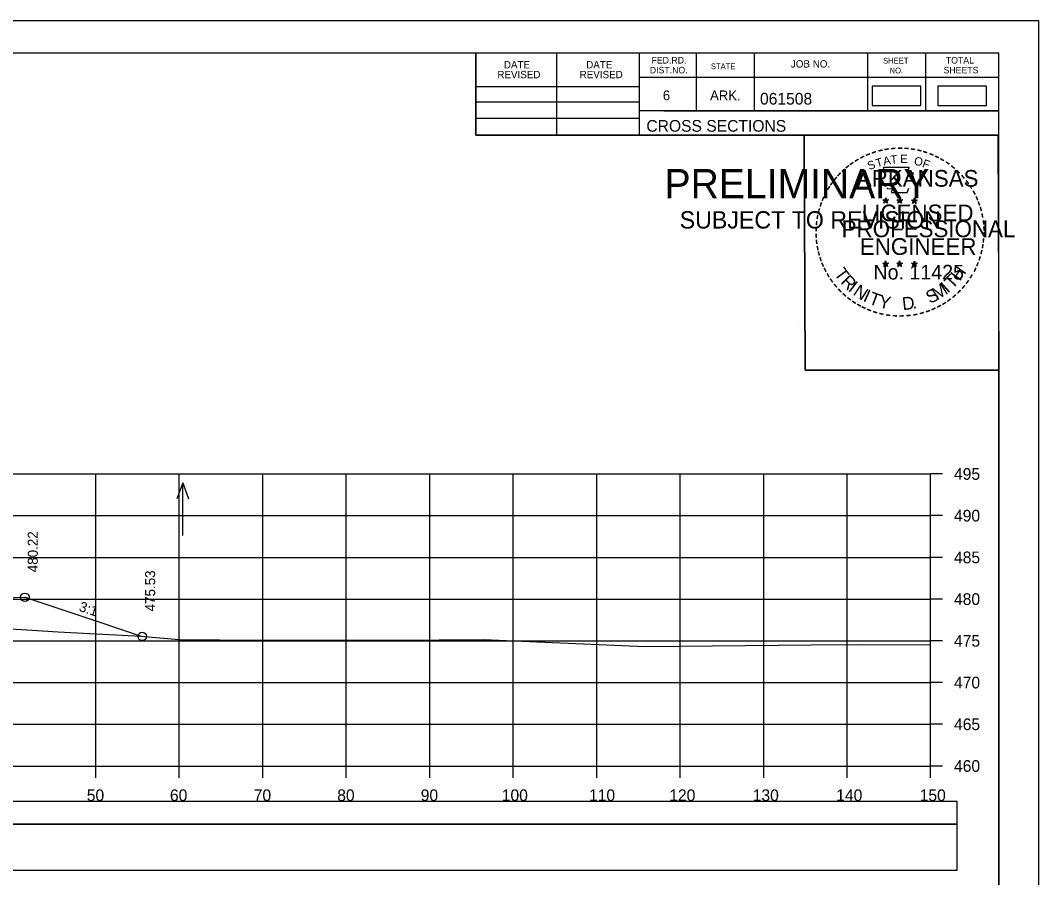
# Model space of a CAD drawing. Extents: x 1371057 to 1372761, y 380005 to 390517.
# Drawn here: x 1371601.8 to 1371723.8, y 382249.1 to 382351.8 of the extents above; entities that cross this region are included whole.
import ezdxf

# ---------------------------------------------------------------- set-up
doc = ezdxf.new("R2010")
doc.units = 0
for name, color, linetype in [('R_Axis', 7, 'Continuous'), ('R_Axis Annot', 7, 'Continuous'), ('R_Border', 7, 'Continuous'), ('R_Border PE', 7, 'Continuous'), ('R_Border Prem', 7, 'Continuous'), ('R_Detour', 7, 'Continuous'), ('R_Dimension', 7, 'Continuous'), ('R_Exist Surface', 7, 'Continuous'), ('R_Fin Surface', 7, 'Continuous'), ('R_Grid', 7, 'Continuous'), ('R_No Plot', 7, 'Continuous'), ('R_Water Annot', 7, 'Continuous'), ('R_Xsect Elev', 7, 'Continuous'), ('R_Xsect Slope', 7, 'Continuous')]:
    doc.layers.add(name, color=color, linetype=linetype)

msp = doc.modelspace()

# ---------------------------------------------------------------- linework, layer by layer
at = {"layer": 'R_Axis'}
for p, q in [((1371710.87, 382262.44), (1371710.87, 382297.44)), ((1371712.27, 382297.44), (1371710.87, 382297.44)), ((1371712.27, 382292.44), (1371710.87, 382292.44)), ((1371712.27, 382287.44), (1371710.87, 382287.44)), ((1371712.27, 382282.44), (1371710.87, 382282.44)), ((1371712.27, 382277.44), (1371710.87, 382277.44)), ((1371712.27, 382272.44), (1371710.87, 382272.44)), ((1371712.27, 382267.44), (1371710.87, 382267.44)), ((1371410.87, 382262.44), (1371710.87, 382262.44)), ((1371610.87, 382261.04), (1371610.87, 382262.44)), ((1371620.87, 382261.04), (1371620.87, 382262.44)), ((1371630.87, 382261.04), (1371630.87, 382262.44)), ((1371640.87, 382261.04), (1371640.87, 382262.44)), ((1371650.87, 382261.04), (1371650.87, 382262.44)), ((1371660.87, 382261.04), (1371660.87, 382262.44)), ((1371670.87, 382261.04), (1371670.87, 382262.44)), ((1371680.87, 382261.04), (1371680.87, 382262.44)), ((1371690.87, 382261.04), (1371690.87, 382262.44)), ((1371700.87, 382261.04), (1371700.87, 382262.44)), ((1371710.87, 382261.04), (1371710.87, 382262.44)), ((1371712.27, 382262.44), (1371710.87, 382262.44))]:
    msp.add_line(p, q, dxfattribs=at)
at = {"layer": 'R_Border'}
for p, q in [((1371402.87, 382347.9), (1371719.05, 382347.9)), ((1371656.41, 382338.02), (1371656.41, 382347.9)), ((1371666.09, 382338.02), (1371666.09, 382347.9)), ((1371675.95, 382347.9), (1371675.95, 382338.02)), ((1371682.79, 382347.9), (1371682.79, 382340.96)), ((1371689.73, 382347.9), (1371689.73, 382340.96)), ((1371703.31, 382347.9), (1371703.31, 382340.96)), ((1371710.25, 382347.9), (1371710.25, 382340.96)), ((1371719.05, 382142.44), (1371719.05, 382347.9)), ((1371719.05, 382344.96), (1371675.95, 382344.96)), ((1371719.05, 382344.98), (1371719.05, 382344.98)), ((1371656.41, 382343.88), (1371675.95, 382343.88)), ((1371656.41, 382342.02), (1371675.95, 382342.02)), ((1371656.41, 382340.08), (1371675.95, 382340.08)), ((1371719.05, 382340.96), (1371675.95, 382340.96)), ((1371678.91, 382340.96), (1371719.05, 382340.96)), ((1371719.05, 382338.02), (1371656.41, 382338.02))]:
    msp.add_line(p, q, dxfattribs=at)
at = {"layer": 'R_Border PE'}
for p, q in [((1371705.14, 382330.27), (1371705.49, 382330.16)), ((1371705.14, 382330.27), (1371705.39, 382330.23)), ((1371705.14, 382330.27), (1371705.37, 382330.15)), ((1371705.27, 382329.87), (1371705.49, 382330.16)), ((1371705.27, 382329.87), (1371705.4, 382330.11)), ((1371705.27, 382329.87), (1371705.48, 382330.08)), ((1371705.49, 382330.53), (1371705.45, 382330.28)), ((1371705.7, 382329.87), (1371705.48, 382330.08)), ((1371705.49, 382330.16), (1371705.49, 382330.53)), ((1371705.49, 382330.53), (1371705.54, 382330.28)), ((1371705.83, 382330.27), (1371705.49, 382330.16)), ((1371705.7, 382329.87), (1371705.49, 382330.16)), ((1371705.83, 382330.27), (1371705.55, 382330.23)), ((1371705.7, 382329.87), (1371705.56, 382330.16)), ((1371705.83, 382330.27), (1371705.63, 382330.17)), ((1371706.81, 382330.27), (1371707.16, 382330.16)), ((1371706.81, 382330.27), (1371707.06, 382330.23)), ((1371706.81, 382330.27), (1371707.04, 382330.15)), ((1371706.94, 382329.87), (1371707.16, 382330.16)), ((1371706.94, 382329.87), (1371707.07, 382330.11)), ((1371706.94, 382329.87), (1371707.15, 382330.08)), ((1371707.16, 382330.53), (1371707.12, 382330.28)), ((1371707.37, 382329.87), (1371707.15, 382330.08)), ((1371707.16, 382330.16), (1371707.16, 382330.53)), ((1371707.16, 382330.53), (1371707.21, 382330.28)), ((1371707.5, 382330.27), (1371707.16, 382330.16)), ((1371707.37, 382329.87), (1371707.16, 382330.16)), ((1371707.5, 382330.27), (1371707.22, 382330.23)), ((1371707.37, 382329.87), (1371707.23, 382330.16)), ((1371707.5, 382330.27), (1371707.3, 382330.17)), ((1371708.57, 382330.26), (1371708.92, 382330.15)), ((1371708.57, 382330.26), (1371708.82, 382330.22)), ((1371708.57, 382330.26), (1371708.81, 382330.14)), ((1371708.7, 382329.85), (1371708.92, 382330.15)), ((1371708.7, 382329.85), (1371708.83, 382330.1)), ((1371708.7, 382329.85), (1371708.92, 382330.07)), ((1371708.92, 382330.52), (1371708.88, 382330.26)), ((1371708.92, 382330.15), (1371708.92, 382330.52)), ((1371708.92, 382330.52), (1371708.97, 382330.27)), ((1371709.27, 382330.26), (1371708.92, 382330.15)), ((1371709.13, 382329.85), (1371708.92, 382330.15)), ((1371709.13, 382329.85), (1371708.92, 382330.07)), ((1371709.27, 382330.26), (1371708.98, 382330.21)), ((1371709.13, 382329.85), (1371709, 382330.15)), ((1371709.27, 382330.26), (1371709.06, 382330.16)), ((1371705.13, 382322.7), (1371705.48, 382322.59)), ((1371705.13, 382322.7), (1371705.39, 382322.66)), ((1371705.13, 382322.7), (1371705.37, 382322.58)), ((1371705.48, 382322.96), (1371705.44, 382322.7)), ((1371705.48, 382322.59), (1371705.48, 382322.96)), ((1371705.48, 382322.96), (1371705.53, 382322.71)), ((1371705.83, 382322.7), (1371705.48, 382322.59)), ((1371705.83, 382322.7), (1371705.54, 382322.65)), ((1371705.83, 382322.7), (1371705.63, 382322.6)), ((1371706.8, 382322.7), (1371707.15, 382322.59)), ((1371706.8, 382322.7), (1371707.06, 382322.66)), ((1371706.8, 382322.7), (1371707.04, 382322.58)), ((1371707.15, 382322.96), (1371707.11, 382322.7)), ((1371707.15, 382322.59), (1371707.15, 382322.96)), ((1371707.15, 382322.96), (1371707.2, 382322.71)), ((1371707.5, 382322.7), (1371707.15, 382322.59)), ((1371707.5, 382322.7), (1371707.21, 382322.65)), ((1371707.5, 382322.7), (1371707.29, 382322.6)), ((1371708.57, 382322.69), (1371708.92, 382322.58)), ((1371708.57, 382322.69), (1371708.82, 382322.65)), ((1371708.57, 382322.69), (1371708.81, 382322.57)), ((1371708.92, 382322.95), (1371708.88, 382322.69)), ((1371708.92, 382322.58), (1371708.92, 382322.95)), ((1371708.92, 382322.95), (1371708.97, 382322.7)), ((1371709.27, 382322.69), (1371708.92, 382322.58)), ((1371709.27, 382322.69), (1371708.98, 382322.64)), ((1371709.27, 382322.69), (1371709.06, 382322.59)), ((1371705.27, 382322.29), (1371705.48, 382322.59)), ((1371705.27, 382322.29), (1371705.39, 382322.54)), ((1371705.27, 382322.29), (1371705.48, 382322.51)), ((1371705.7, 382322.29), (1371705.48, 382322.59)), ((1371705.7, 382322.29), (1371705.48, 382322.51)), ((1371705.7, 382322.29), (1371705.56, 382322.58)), ((1371706.94, 382322.29), (1371707.15, 382322.59)), ((1371706.94, 382322.29), (1371707.06, 382322.54)), ((1371706.94, 382322.29), (1371707.15, 382322.51)), ((1371707.36, 382322.29), (1371707.15, 382322.59)), ((1371707.36, 382322.29), (1371707.15, 382322.51)), ((1371707.36, 382322.29), (1371707.23, 382322.58)), ((1371708.7, 382322.28), (1371708.92, 382322.58)), ((1371708.7, 382322.28), (1371708.83, 382322.53)), ((1371708.7, 382322.28), (1371708.92, 382322.5)), ((1371709.13, 382322.28), (1371708.92, 382322.58)), ((1371709.13, 382322.28), (1371708.92, 382322.5)), ((1371709.13, 382322.28), (1371708.99, 382322.57))]:
    msp.add_line(p, q, dxfattribs=at)
for points in [[(1371705.18, 382334.15), (1371705.45, 382333.33)], [(1371708.69, 382333.23), (1371708.83, 382333.51), (1371708.15, 382333.49), (1371708.29, 382334.15), (1371705.18, 382334.15)], [(1371705.67, 382331.73), (1371705.67, 382331.64), (1371706.23, 382331.62), (1371706.18, 382331.15), (1371708.05, 382331.15), (1371708.25, 382331.69)], [(1371705.49, 382330.53), (1371705.7, 382329.87), (1371705.14, 382330.27), (1371705.83, 382330.27), (1371705.27, 382329.87), (1371705.49, 382330.53)], [(1371707.16, 382330.53), (1371707.37, 382329.87), (1371706.81, 382330.27), (1371707.5, 382330.27), (1371706.94, 382329.87), (1371707.16, 382330.53)], [(1371708.92, 382330.52), (1371709.13, 382329.85), (1371708.57, 382330.26), (1371709.27, 382330.26), (1371708.7, 382329.85), (1371708.92, 382330.52)], [(1371705.48, 382322.96), (1371705.7, 382322.29), (1371705.13, 382322.7), (1371705.83, 382322.7), (1371705.27, 382322.29), (1371705.48, 382322.96)], [(1371707.15, 382322.96), (1371707.36, 382322.29), (1371706.8, 382322.7), (1371707.5, 382322.7), (1371706.94, 382322.29), (1371707.15, 382322.96)], [(1371708.92, 382322.95), (1371709.13, 382322.28), (1371708.57, 382322.69), (1371709.27, 382322.69), (1371708.7, 382322.28), (1371708.92, 382322.95)]]:
    msp.add_lwpolyline(points, dxfattribs=at)
for centre, radius in [((1371705.49, 382330.16), 0.172), ((1371705.49, 382330.16), 0.145), ((1371705.49, 382330.16), 0.116), ((1371705.49, 382330.16), 0.0991), ((1371705.49, 382330.16), 0.0747), ((1371705.49, 382330.16), 0.0495), ((1371705.49, 382330.16), 0.0296), ((1371707.16, 382330.16), 0.172), ((1371707.16, 382330.16), 0.145), ((1371707.16, 382330.16), 0.116), ((1371707.16, 382330.16), 0.0991), ((1371707.16, 382330.16), 0.0747), ((1371707.16, 382330.16), 0.0495), ((1371707.16, 382330.16), 0.0296), ((1371708.92, 382330.15), 0.172), ((1371708.92, 382330.15), 0.145), ((1371708.92, 382330.15), 0.116), ((1371708.92, 382330.15), 0.0991), ((1371708.92, 382330.15), 0.0747), ((1371708.92, 382330.15), 0.0495), ((1371708.92, 382330.15), 0.0296), ((1371705.48, 382322.59), 0.172), ((1371705.48, 382322.59), 0.145), ((1371705.48, 382322.59), 0.116), ((1371705.48, 382322.59), 0.0991), ((1371707.15, 382322.59), 0.172), ((1371707.15, 382322.59), 0.145), ((1371707.15, 382322.59), 0.116), ((1371707.15, 382322.59), 0.0991), ((1371708.92, 382322.58), 0.172), ((1371708.92, 382322.58), 0.145), ((1371708.92, 382322.58), 0.116), ((1371705.48, 382322.59), 0.0747), ((1371705.48, 382322.59), 0.0495), ((1371705.48, 382322.59), 0.0296), ((1371707.15, 382322.59), 0.0747), ((1371707.15, 382322.59), 0.0495), ((1371707.15, 382322.59), 0.0296), ((1371708.92, 382322.58), 0.0991), ((1371708.92, 382322.58), 0.0747), ((1371708.92, 382322.58), 0.0495), ((1371708.92, 382322.58), 0.0296)]:
    msp.add_circle(centre, radius, dxfattribs=at)
at = {"layer": 'R_Detour'}
msp.add_lwpolyline([(1371407.72, 382255.49), (1371714.03, 382255.49), (1371714.03, 382258.19), (1371407.72, 382258.19)], close=True, dxfattribs=at)
at = {"layer": 'R_Dimension'}
for points in [[(1371703.87, 382341.61), (1371709.7, 382341.61), (1371709.7, 382343.92), (1371703.87, 382343.92)], [(1371711.74, 382341.61), (1371717.57, 382341.61), (1371717.57, 382343.92), (1371711.74, 382343.92)], [(1371407.72, 382249.96), (1371714.03, 382249.96), (1371714.03, 382255.49), (1371407.72, 382255.49)]]:
    msp.add_lwpolyline(points, close=True, dxfattribs=at)
at = {"layer": 'R_Exist Surface'}
msp.add_lwpolyline([(1371597.54, 382279.09), (1371606.38, 382278.5), (1371616.25, 382277.99), (1371621.29, 382277.55), (1371625.73, 382277.55), (1371646.32, 382277.53), (1371647.2, 382277.52), (1371652.01, 382277.54), (1371655.8, 382277.55), (1371657.32, 382277.58), (1371675.7, 382276.8), (1371676.8, 382276.76), (1371696.54, 382276.97), (1371702.69, 382276.99), (1371710.87, 382276.97)], dxfattribs=at)
at = {"layer": 'R_Fin Surface'}
msp.add_lwpolyline([(1371599.81, 382282.61), (1371602.37, 382282.66), (1371610.99, 382279.78), (1371616.43, 382277.97)], dxfattribs=at)
at = {"layer": 'R_Grid'}
for p, q in [((1371410.87, 382297.44), (1371710.87, 382297.44)), ((1371610.87, 382262.44), (1371610.87, 382297.44)), ((1371620.87, 382262.44), (1371620.87, 382297.44)), ((1371630.87, 382262.44), (1371630.87, 382297.44)), ((1371640.87, 382262.44), (1371640.87, 382297.44)), ((1371650.87, 382262.44), (1371650.87, 382297.44)), ((1371660.87, 382262.44), (1371660.87, 382297.44)), ((1371670.87, 382262.44), (1371670.87, 382297.44)), ((1371680.87, 382262.44), (1371680.87, 382297.44)), ((1371690.87, 382262.44), (1371690.87, 382297.44)), ((1371700.87, 382262.44), (1371700.87, 382297.44)), ((1371710.87, 382262.44), (1371710.87, 382297.44)), ((1371410.87, 382292.44), (1371710.87, 382292.44)), ((1371410.87, 382287.44), (1371710.87, 382287.44)), ((1371410.87, 382282.44), (1371710.87, 382282.44)), ((1371410.87, 382277.44), (1371710.87, 382277.44)), ((1371410.87, 382272.44), (1371710.87, 382272.44)), ((1371410.87, 382267.44), (1371710.87, 382267.44)), ((1371410.87, 382262.44), (1371710.87, 382262.44))]:
    msp.add_line(p, q, dxfattribs=at)
at = {"layer": 'R_No Plot'}
for p, q in [((1371390.47, 382351.79), (1371723.8, 382351.79)), ((1371695.09, 382315.56), (1371695.09, 382315.56))]:
    msp.add_line(p, q, dxfattribs=at)
for points in [[(1371390.46, 382351.79), (1371723.8, 382351.79), (1371723.8, 382138.46), (1371390.46, 382138.46)], [(1371636.79, 382347.9), (1371656.41, 382347.9), (1371656.41, 382338.02), (1371672.52, 382338.02), (1371695.72, 382338.02), (1371695.84, 382309.86), (1371719.05, 382309.86), (1371719.05, 382142.44), (1371402.87, 382142.44), (1371402.87, 382347.9)], [(1371695.72, 382338.02), (1371718.93, 382338.02), (1371719.05, 382309.86), (1371695.84, 382309.86)]]:
    msp.add_lwpolyline(points, close=True, dxfattribs=at)
for centre in [(1371602.37, 382282.66), (1371616.43, 382277.97)]:
    msp.add_circle(centre, 0.5, dxfattribs=at)
at = {"layer": 'R_Water Annot'}
for p, q in [((1371621.29, 382296.36), (1371620.59, 382294.44)), ((1371621.29, 382290.08), (1371621.29, 382296.36)), ((1371621.29, 382296.36), (1371621.99, 382294.44))]:
    msp.add_line(p, q, dxfattribs=at)

# ---------------------------------------------------------------- texts
at = {"layer": 'R_Axis Annot'}
for s, p in [('495', (1371713.67, 382296.74)), ('490', (1371713.67, 382291.74)), ('485', (1371713.67, 382286.74)), ('480', (1371713.67, 382281.74)), ('475', (1371713.67, 382276.74)), ('470', (1371713.67, 382271.74)), ('465', (1371713.67, 382266.74)), ('460', (1371713.67, 382261.74)), ('50', (1371609.79, 382258.24)), ('60', (1371619.75, 382258.24)), ('70', (1371629.79, 382258.24)), ('80', (1371639.79, 382258.24)), ('90', (1371649.79, 382258.24)), ('100', (1371659.5, 382258.24)), ('110', (1371669.95, 382258.24)), ('120', (1371679.56, 382258.24)), ('130', (1371689.56, 382258.24)), ('140', (1371699.56, 382258.24)), ('150', (1371709.56, 382258.24))]:
    msp.add_text(s, height=1.4, dxfattribs=at).set_placement(p)
at = {"layer": 'R_Border'}
for s, height, p in [('FED.RD.', 0.782, (1371677.43, 382346.62)), ('SHEET', 0.684, (1371705.17, 382346.62)), ('TOTAL', 0.782, (1371712.69, 382346.62)), ('DATE', 0.879, (1371659.75, 382346.04)), ('DATE', 0.879, (1371669.61, 382346.04)), ('DIST.NO.', 0.782, (1371677.23, 382345.44)), ('STATE', 0.684, (1371684.55, 382345.94)), ('JOB NO.', 0.879, (1371694.13, 382346.14)), ('NO.', 0.684, (1371705.95, 382345.44)), ('SHEETS', 0.782, (1371712.41, 382345.44)), ('REVISED', 0.879, (1371658.97, 382344.86)), ('REVISED', 0.879, (1371668.83, 382344.86)), ('6', 1.17, (1371678.79, 382342.22)), ('ARK.', 1.172, (1371684.45, 382342.22)), ('061508', 1.4, (1371690.43, 382341.7)), ('CROSS SECTIONS', 1.4, (1371676.82, 382338.45))]:
    msp.add_text(s, height=height, rotation=360, dxfattribs=at).set_placement(p)
at = {"layer": 'R_Border PE'}
for s, height, rotation, p in [('-', 1.6, 19.1761, (1371703.93, 382335.28)), ('-', 1.6, 13.6301, (1371704.68, 382335.52)), ('-', 1.6, 10.2193, (1371705.35, 382335.68)), ('-', 1.6, 5.8968, (1371706.08, 382335.79)), ('-', 1.6, 0.1862, (1371706.86, 382335.86)), ('-', 1.6, 357.743, (1371707.58, 382335.85)), ('-', 1.6, 352.1617, (1371708.32, 382335.8)), ('-', 1.6, 347.2049, (1371709.04, 382335.68)), ('-', 1.6, 342.3362, (1371709.68, 382335.53)), ('-', 1.6, 34.0636, (1371702.06, 382334.32)), ('-', 1.6, 28.7918, (1371702.66, 382334.69)), ('-', 1.6, 24.3072, (1371703.29, 382335.01)), ('S', 1, 21.594, (1371703.53, 382333.83)), ('T', 1, 16.4036, (1371704.45, 382334.16)), ('A', 1, 11.2132, (1371705.27, 382334.41)), ('T', 1, 6.0228, (1371706.12, 382334.58)), ('E', 1, 0.8323, (1371707.23, 382334.69)), ('O', 1, 350.4515, (1371708.83, 382334.48)), ('F', 1, 340.0707, (1371709.79, 382334.25)), ('-', 1.6, 337.8551, (1371710.41, 382335.3)), ('-', 1.6, 334.1211, (1371711.04, 382335.03)), ('-', 1.6, 329.6409, (1371711.62, 382334.75)), ('-', 1.6, 325.8627, (1371712.26, 382334.39)), ('-', 1.6, 42.9622, (1371700.58, 382333.13)), ('-', 1.6, 38.9507, (1371701.01, 382333.55)), ('-', 1.6, 36.2317, (1371701.48, 382333.93)), ('ARKANSAS', 2, 360, (1371702.03, 382331.86)), ('-', 1.6, 320.5297, (1371712.87, 382333.96)), ('-', 1.6, 315.5786, (1371713.47, 382333.47)), ('-', 1.6, 54.2325, (1371699.31, 382331.6)), ('-', 1.6, 50.6142, (1371699.72, 382332.17)), ('-', 1.6, 48.423, (1371700.13, 382332.66)), ('-', 1.6, 309.8797, (1371714.04, 382332.92)), ('-', 1.6, 306.6522, (1371714.57, 382332.32)), ('-', 1.6, 62.8713, (1371698.67, 382330.46)), ('-', 1.6, 58.0706, (1371698.99, 382331.08)), ('-', 1.4, 303.6753, (1371715.05, 382331.75)), ('-', 1.6, 299.6684, (1371715.37, 382331.15)), ('-', 1.6, 72.3945, (1371698.2, 382329.22)), ('-', 1.6, 67.7743, (1371698.41, 382329.85)), ('DWB', 0.01, 360, (1371705.47, 382330.16)), ('DWB', 0.01, 360, (1371707.14, 382330.16)), ('DWB', 0.01, 360, (1371708.91, 382330.15)), ('-', 1.6, 294.6628, (1371715.7, 382330.54)), ('-', 1.6, 290.5728, (1371715.95, 382329.96)), ('-', 1.6, 75.461, (1371698, 382328.51)), ('LICENSED', 2, 360, (1371702.63, 382327.72)), ('-', 1.6, 285.1233, (1371716.19, 382329.38)), ('-', 1.6, 85.1863, (1371697.79, 382327.1)), ('-', 1.6, 81.2013, (1371697.87, 382327.79)), ('PROFESSIONAL', 2, 360, (1371700.21, 382325.81)), ('-', 1.6, 280.5493, (1371716.39, 382328.64)), ('-', 1.6, 276.5962, (1371716.55, 382327.87)), ('-', 1.6, 89.0622, (1371697.77, 382326.4)), ('-', 1.6, 274.3301, (1371716.61, 382327.15)), ('-', 1.6, 269.9407, (1371716.64, 382326.51)), ('-', 1.6, 94.1959, (1371697.8, 382325.68)), ('-', 1.6, 98.9479, (1371697.87, 382325.01)), ('ENGINEER', 2, 360, (1371702.39, 382323.69)), ('-', 1.6, 263.5172, (1371716.62, 382325.85)), ('-', 1.6, 101.7149, (1371698.01, 382324.28)), ('-', 1.6, 105.4578, (1371698.17, 382323.68)), ('-', 1.6, 255.7626, (1371716.44, 382324.52)), ('-', 1.6, 260.9953, (1371716.55, 382325.19)), ('-', 1.6, 109.0874, (1371698.38, 382323.05)), ('-', 1.6, 114.0643, (1371698.64, 382322.45)), ('-', 1.6, 247.8887, (1371716.04, 382323.12)), ('-', 1.6, 252.8681, (1371716.26, 382323.8)), ('-', 1.6, 115.7289, (1371698.94, 382321.84)), ('-', 1.6, 120.4471, (1371699.3, 382321.25)), ('T', 1.54, 306.0406, (1371699.24, 382321.43)), ('No. 11425', 1.757, 360, (1371704.02, 382320.74)), ('DWB', 0.01, 360, (1371705.47, 382322.59)), ('DWB', 0.01, 360, (1371707.14, 382322.59)), ('DWB', 0.01, 360, (1371708.91, 382322.58)), ('H', 1.54, 54.6088, (1371714.36, 382320.46)), ('-', 1.6, 244.6197, (1371715.78, 382322.49)), ('-', 1.6, 125.8934, (1371699.7, 382320.69)), ('-', 1.6, 130.7181, (1371700.17, 382320.14)), ('R', 1.54, 314.005, (1371700, 382320.38)), ('I', 1.54, 321.9694, (1371700.9, 382319.45)), ('M', 1.54, 32.6563, (1371711.63, 382318.2)), ('I', 1.54, 42.1136, (1371712.91, 382319.04)), ('T', 1.54, 46.6444, (1371713.47, 382319.52)), ('-', 1.6, 233.8452, (1371714.98, 382321.09)), ('-', 1.6, 239.0712, (1371715.38, 382321.74)), ('-', 1.6, 134.2238, (1371700.68, 382319.59)), ('-', 1.6, 138.9338, (1371701.21, 382319.13)), ('N', 1.54, 326.5002, (1371701.47, 382318.98)), ('I', 1.54, 335.3603, (1371702.68, 382318.19)), ('T', 1.54, 339.8912, (1371703.34, 382317.86)), ('S', 1.54, 26.9312, (1371710.79, 382317.79)), ('-', 1.6, 225.7653, (1371714.07, 382319.96)), ('-', 1.6, 231.2538, (1371714.55, 382320.52)), ('-', 1.6, 144.6463, (1371701.76, 382318.72)), ('-', 1.6, 148.0898, (1371702.32, 382318.35)), ('-', 1.6, 151.5704, (1371702.9, 382318.03)), ('Y', 1.54, 347.8556, (1371704.56, 382317.42)), ('D', 1.54, 6.3969, (1371707.54, 382317.06)), ('-', 1.6, 212.2491, (1371712.47, 382318.59)), ('-', 1.6, 215.7363, (1371713, 382318.98)), ('-', 1.6, 221.0851, (1371713.55, 382319.45)), ('-', 1.6, 154.6002, (1371703.43, 382317.78)), ('-', 1.6, 158.5612, (1371704.05, 382317.53)), ('-', 1.6, 162.7983, (1371704.74, 382317.31)), ('-', 1.6, 167.5555, (1371705.45, 382317.15)), ('-', 1.6, 173.1155, (1371706.22, 382317.04)), ('-', 1.6, 191.2858, (1371709.26, 382317.21)), ('.', 1.54, 13.7642, (1371708.74, 382317.19)), ('-', 1.6, 195.4743, (1371709.99, 382317.41)), ('-', 1.6, 200.7184, (1371710.67, 382317.65)), ('-', 1.6, 204.2516, (1371711.29, 382317.93)), ('-', 1.6, 207.3568, (1371711.91, 382318.25)), ('-', 1.6, 176.5183, (1371706.97, 382316.99)), ('-', 1.6, 181.5918, (1371707.72, 382317)), ('-', 1.6, 185.8167, (1371708.52, 382317.08))]:
    msp.add_text(s, height=height, rotation=rotation, dxfattribs=at).set_placement(p)
at = {"layer": 'R_Border Prem'}
for s, height, p in [('PRELIMINARY', 3.5, (1371679, 382330.48)), ('DWB', 0.01, (1371679.75, 382332.33)), ('SUBJECT TO REVISION', 2.0751, (1371680.81, 382326.85))]:
    msp.add_text(s, height=height, rotation=360, dxfattribs=at).set_placement(p)
at = {"layer": 'R_Xsect Elev'}
for s, p in [('480.22', (1371603.92, 382285.66)), ('475.53', (1371617.98, 382280.97))]:
    msp.add_text(s, height=1.2, rotation=90, dxfattribs=at).set_placement(p)
at = {"layer": 'R_Xsect Slope'}
msp.add_text('3:1', height=1.2, rotation=341.5633, dxfattribs=at).set_placement((1371608.77, 382281.05))

doc.saveas('drawing.dxf')
